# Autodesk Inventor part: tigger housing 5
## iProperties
Created: 2006-04
Part Number: tigger housing 5
Document SubType Name: Modeling
Designer: Калинин
Author: Калинин
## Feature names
1. Выдавливание1 [Extrusion]
2. Сопряжение1 [Fillet]
3. Сопряжение2 [Fillet]
